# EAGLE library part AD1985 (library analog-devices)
AC ?97 SoundMAX® Codec Auto generated by make-symbol-device-package-bsdl.ulp Rev. 33 Source: http://www.analog.com/static/imported-files/data_sheets/AD1985.pdf
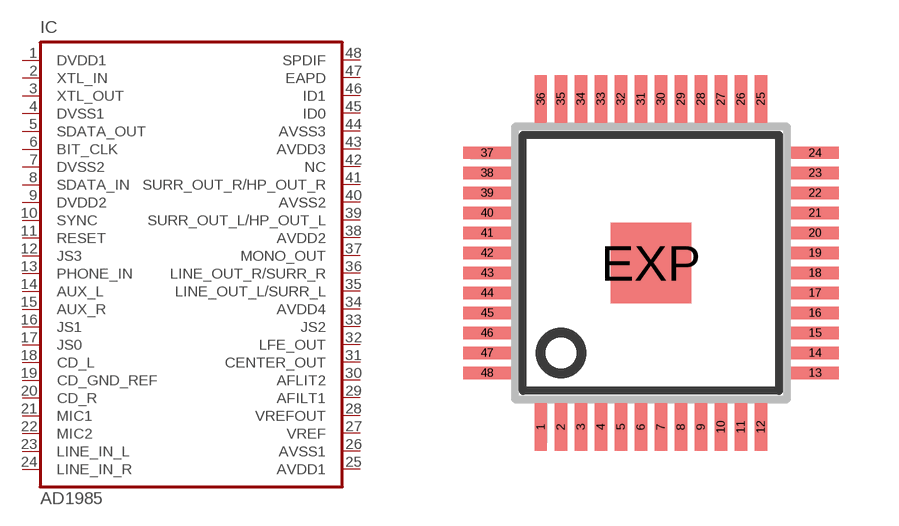
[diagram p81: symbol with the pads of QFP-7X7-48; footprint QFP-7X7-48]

Designator prefix IC

## AD1985 (OC_FARNELL: unknown; OC_NEWARK: unknown)  [QFP-7X7-48]
1  DVDD1  in
2  XTL_IN  in
3  XTL_OUT  out
4  DVSS1  in
5  SDATA_OUT  in
6  BIT_CLK  in
7  DVSS2  in
8  SDATA_IN  out
9  DVDD2  in
10  SYNC  in
11  RESET  in
12  JS3  in
13  PHONE_IN  in
14  AUX_L  in
15  AUX_R  in
16  JS1  in
17  JS0  in
18  CD_L  in
19  CD_GND_REF  in
20  CD_R  in
21  MIC1  in
22  MIC2  in
23  LINE_IN_L  in
24  LINE_IN_R  in
25  AVDD1  in
26  AVSS1  in
27  VREF  out
28  VREFOUT  out
29  AFILT1  out
30  AFLIT2  out
31  CENTER_OUT
32  LFE_OUT
33  JS2  in
34  AVDD4  in
35  LINE_OUT_L/SURR_L  out
36  LINE_OUT_R/SURR_R  out
37  MONO_OUT  out
38  AVDD2  in
39  SURR_OUT_L/HP_OUT_L  out
40  AVSS2  in
41  SURR_OUT_R/HP_OUT_R  out
42  NC  nc
43  AVDD3  in
44  AVSS3  in
45  ID0  in
46  ID1  in
47  EAPD  out
48  SPDIF  out

## Footprint QFP-7X7-48 (pad centres in mm)
TQFP48 7x7 Thin Plastic Quad Flat Package, Exposed Pad, TQFP/EP Source: www.analog.com/UploadedFiles/Data_Sheets/33830397585263AD9859_0.pdf
smd 0.3 x 1.2: 1 -2.75,-4.1; 2 -2.25,-4.1; 3 -1.75,-4.1; 4 -1.25,-4.1; 5 -0.75,-4.1; 6 -0.25,-4.1; 7 0.25,-4.1; 8 0.75,-4.1; 9 1.25,-4.1; 10 1.75,-4.1; 11 2.25,-4.1; 12 2.75,-4.1; 25 2.75,4.1; 26 2.25,4.1; 27 1.75,4.1; 28 1.25,4.1; 29 0.75,4.1; 30 0.25,4.1; 31 -0.25,4.1; 32 -0.75,4.1; 33 -1.25,4.1; 34 -1.75,4.1; 35 -2.25,4.1; 36 -2.75,4.1
smd 1.2 x 0.3: 13 4.1,-2.75; 14 4.1,-2.25; 15 4.1,-1.75; 16 4.1,-1.25; 17 4.1,-0.75; 18 4.1,-0.25; 19 4.1,0.25; 20 4.1,0.75; 21 4.1,1.25; 22 4.1,1.75; 23 4.1,2.25; 24 4.1,2.75; 37 -4.1,2.75; 38 -4.1,2.25; 39 -4.1,1.75; 40 -4.1,1.25; 41 -4.1,0.75; 42 -4.1,0.25; 43 -4.1,-0.25; 44 -4.1,-0.75; 45 -4.1,-1.25; 46 -4.1,-1.75; 47 -4.1,-2.25; 48 -4.1,-2.75
smd 2 x 2: EXP 0,0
